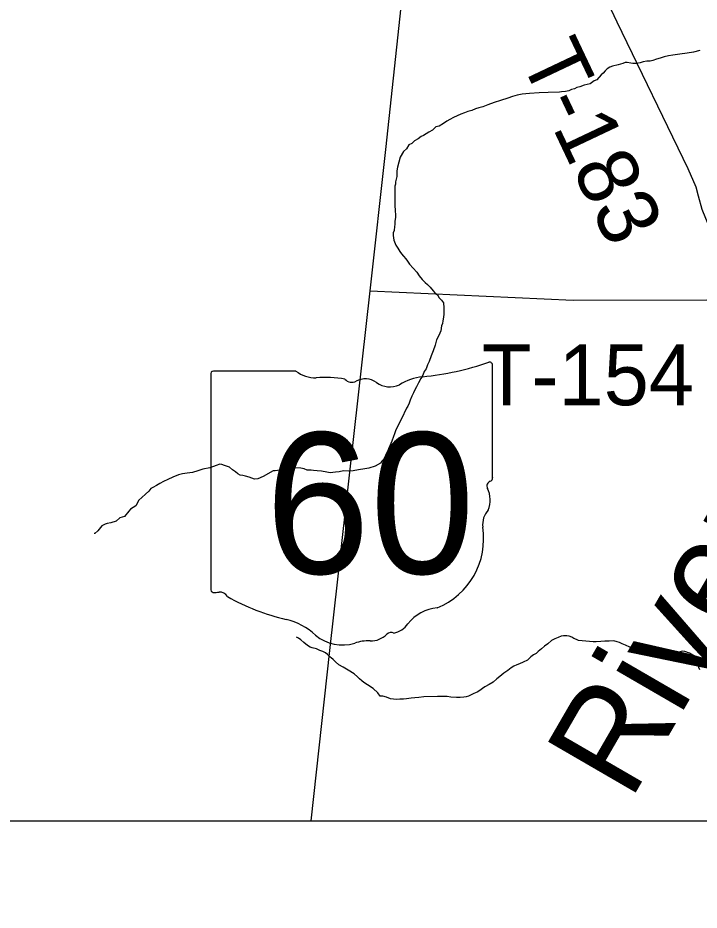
# Model space of a CAD drawing. Extents: x 0 to 34, y 0 to 22.
# Drawn here: x 4.849 to 5.486, y 15.642 to 16.477 of the extents above; entities that cross this region are included whole.
import ezdxf

# ---------------------------------------------------------------- set-up
doc = ezdxf.new("R2010")
doc.units = 0
for name, color, linetype in [('GM_X_Corporation', 7, 'Continuous'), ('GM_X_Major_River_Text', 7, 'Continuous'), ('GM_X_Minor_River', 7, 'Continuous'), ('GM_X_State_Location', 7, 'Continuous'), ('GM_X_State_Route', 7, 'Continuous'), ('GM_X_State_Shield', 7, 'Continuous'), ('GM_X_Township_Road', 7, 'Continuous'), ('GM_X_Township_Road_Text', 7, 'Continuous'), ('SH_Text', 7, 'Continuous')]:
    doc.layers.add(name, color=color, linetype=linetype)

msp = doc.modelspace()

# ---------------------------------------------------------------- linework, layer by layer
at = {"layer": 'GM_X_Corporation'}
msp.add_lwpolyline([(3.69009, 15.2048), (3.69009, 15.72564), (5.90994, 15.72564), (5.90994, 15.21376)], dxfattribs=at)
at = {"layer": 'GM_X_Minor_River'}
for points in [[(5.46154, 16.44181), (5.45735, 16.4411), (5.45353, 16.44001), (5.44972, 16.43891), (5.44629, 16.43781), (5.44285, 16.43671), (5.44018, 16.43598), (5.43714, 16.43602), (5.43371, 16.4353), (5.43104, 16.43457), (5.42761, 16.43385), (5.42419, 16.43389), (5.42229, 16.4343), (5.41888, 16.43472), (5.41698, 16.43474), (5.41469, 16.43401), (5.41049, 16.43254), (5.40515, 16.43146), (5.40248, 16.43035), (5.40018, 16.42886), (5.39826, 16.42698), (5.39633, 16.42472), (5.39441, 16.42322), (5.39056, 16.41871), (5.38788, 16.4176), (5.38405, 16.41498), (5.37871, 16.41353), (5.37451, 16.41205), (5.37184, 16.41133), (5.36955, 16.41021), (5.36688, 16.40948), (5.3642, 16.40838), (5.36115, 16.40765), (5.35735, 16.40732), (5.35544, 16.40696), (5.3448, 16.40671), (5.33643, 16.40642), (5.3273, 16.40577), (5.32045, 16.40509), (5.31588, 16.40439), (5.31168, 16.40292), (5.3071, 16.40145), (5.30023, 16.39925), (5.2945, 16.39742), (5.2884, 16.39521), (5.28381, 16.39336), (5.28, 16.39227), (5.27695, 16.39155), (5.27351, 16.39006), (5.2697, 16.38897), (5.26664, 16.38787), (5.2632, 16.38638), (5.25976, 16.38491), (5.25632, 16.38343), (5.25288, 16.38157), (5.2502, 16.38008), (5.24713, 16.37783), (5.24292, 16.37522), (5.23987, 16.3745), (5.23679, 16.37149), (5.23335, 16.36963), (5.23067, 16.36814), (5.22837, 16.36665), (5.22608, 16.36554), (5.22339, 16.36329), (5.21995, 16.36143), (5.21726, 16.35918), (5.21458, 16.35769), (5.21225, 16.35392), (5.20957, 16.35167), (5.20646, 16.34638), (5.20526, 16.34146), (5.20407, 16.33691), (5.20327, 16.3335), (5.2032, 16.32818), (5.202, 16.32325), (5.20197, 16.32097), (5.20157, 16.31907), (5.20155, 16.31717), (5.20152, 16.31451), (5.20147, 16.31109), (5.20143, 16.30767), (5.20139, 16.30387), (5.20136, 16.30159), (5.20134, 16.29969), (5.2017, 16.29778), (5.20167, 16.2955), (5.20202, 16.29284), (5.20198, 16.29018), (5.20155, 16.286), (5.20152, 16.28334), (5.20112, 16.28144), (5.20069, 16.27765), (5.1999, 16.27538), (5.19988, 16.2731), (5.20058, 16.26853), (5.20243, 16.26394), (5.2043, 16.26126), (5.20616, 16.2582), (5.20765, 16.2559), (5.20953, 16.2536)], [(5.48668, 16.44608), (5.48096, 16.44462), (5.47486, 16.44356), (5.46801, 16.4425), (5.46154, 16.44181)], [(5.20953, 16.2536), (5.21178, 16.25129), (5.21327, 16.24899), (5.21514, 16.24631), (5.22189, 16.23862), (5.22413, 16.23518), (5.22713, 16.23172), (5.22976, 16.22903), (5.23202, 16.2271), (5.23465, 16.22479), (5.23727, 16.22134), (5.23877, 16.21942), (5.2414, 16.21749), (5.24289, 16.21481), (5.24514, 16.2125), (5.24702, 16.2102), (5.24734, 16.20525), (5.24727, 16.19955), (5.24685, 16.19652), (5.24643, 16.1931), (5.24602, 16.19082), (5.24524, 16.18855), (5.24442, 16.184), (5.24247, 16.17946), (5.24052, 16.1753), (5.23932, 16.17037), (5.23735, 16.16508), (5.2354, 16.16054), (5.23343, 16.15524), (5.23188, 16.15222), (5.23069, 16.14843), (5.22876, 16.14579), (5.22757, 16.14239), (5.22564, 16.13937), (5.22369, 16.13521), (5.22174, 16.13143), (5.22019, 16.12879), (5.21901, 16.12576), (5.21746, 16.12274), (5.21589, 16.11896), (5.21472, 16.11631), (5.21354, 16.11328), (5.21238, 16.1114), (5.2077, 16.10157), (5.20576, 16.09817), (5.20497, 16.0959), (5.20342, 16.09326), (5.20224, 16.09023), (5.20107, 16.08758), (5.20027, 16.08493), (5.19871, 16.08077), (5.19675, 16.07623), (5.19558, 16.07358), (5.19479, 16.07169), (5.19362, 16.06904), (5.19245, 16.06678), (5.19128, 16.06375), (5.18935, 16.06187), (5.18819, 16.05998), (5.18322, 16.05738), (5.17711, 16.05555), (5.1733, 16.05484), (5.16759, 16.05377), (5.16264, 16.05307), (5.15807, 16.05274), (5.15351, 16.05279), (5.14932, 16.05208), (5.1459, 16.05174), (5.14361, 16.05139), (5.14095, 16.05104), (5.13792, 16.05184), (5.13298, 16.05266), (5.12881, 16.05309), (5.12539, 16.05313), (5.12311, 16.05353), (5.12121, 16.05356), (5.11931, 16.05358), (5.11666, 16.05475), (5.11363, 16.05555), (5.10869, 16.05561), (5.10299, 16.05529), (5.0965, 16.05385), (5.08965, 16.05279), (5.08775, 16.05281), (5.07818, 16.0476), (5.07322, 16.04538), (5.07017, 16.04504), (5.06525, 16.047), (5.06184, 16.0478), (5.05919, 16.04859), (5.05691, 16.049), (5.05464, 16.05016), (5.05239, 16.05209), (5.04975, 16.05402), (5.04674, 16.05634), (5.04219, 16.05791), (5.03954, 16.05871), (5.03765, 16.05911), (5.03421, 16.05801), (5.02849, 16.0558), (5.022, 16.05435)], [(5.022, 16.05435), (5.01705, 16.05289), (5.01209, 16.05143), (5.00714, 16.05073), (5.00295, 16.05002), (4.99914, 16.0493), (4.99379, 16.04709), (4.9892, 16.04486), (4.985, 16.04301), (4.98155, 16.04115), (4.97849, 16.03928), (4.97504, 16.03742), (4.97313, 16.03631), (4.9712, 16.03405), (4.96813, 16.03104), (4.96467, 16.02804), (4.96198, 16.02542), (4.95925, 16.02012), (4.95427, 16.01714), (4.95273, 16.01526), (4.94849, 16.01037), (4.94429, 16.0089), (4.94083, 16.0059), (4.93587, 16.00444), (4.93244, 16.00372), (4.93053, 16.00298), (4.92748, 16.0015), (4.92362, 15.99698), (4.92093, 15.99435), (4.92017, 15.99436)], [(5.17582, 15.85296), (5.17242, 15.8549), (5.17054, 15.85645), (5.16828, 15.85837), (5.1664, 15.8603), (5.16339, 15.86299), (5.15773, 15.86648), (5.1532, 15.8692), (5.14905, 15.87153), (5.14604, 15.87422), (5.14379, 15.87653), (5.14191, 15.87807), (5.13852, 15.88115), (5.13664, 15.8827), (5.134, 15.88387), (5.13135, 15.88504), (5.12832, 15.8866), (5.12415, 15.88741), (5.12226, 15.88819), (5.11962, 15.88974), (5.11623, 15.89244), (5.1136, 15.89475), (5.11134, 15.8963), (5.10945, 15.89746), (5.10945, 15.89746)], [(5.48693, 15.86676), (5.48582, 15.86905), (5.48546, 15.87096), (5.48511, 15.87286), (5.48252, 15.87935), (5.47724, 15.88246), (5.4727, 15.88403), (5.47042, 15.88444), (5.46508, 15.8826), (5.45936, 15.88153), (5.4548, 15.8812), (5.45214, 15.88124), (5.44986, 15.88164), (5.44644, 15.88206), (5.44454, 15.88209), (5.44189, 15.8825), (5.43885, 15.88254), (5.43504, 15.88258), (5.43238, 15.88261), (5.42898, 15.88379), (5.4271, 15.88534), (5.42445, 15.88689), (5.42143, 15.88806), (5.41727, 15.89001), (5.41424, 15.89119), (5.41159, 15.89236), (5.40932, 15.89315), (5.40629, 15.89394), (5.40211, 15.89361), (5.39793, 15.89366), (5.39412, 15.89333), (5.38993, 15.893), (5.38689, 15.89303), (5.38348, 15.89345), (5.37322, 15.89434), (5.37133, 15.89512), (5.36907, 15.89629), (5.36718, 15.89745), (5.36453, 15.89824), (5.36225, 15.89865), (5.35921, 15.89868), (5.35693, 15.89833), (5.35425, 15.89722), (5.35119, 15.89574), (5.34814, 15.89425), (5.34468, 15.89125), (5.34161, 15.88901), (5.33854, 15.88639), (5.33547, 15.88414), (5.33355, 15.88226), (5.33125, 15.88077), (5.32856, 15.8789), (5.32549, 15.8759), (5.32166, 15.87404), (5.31822, 15.87256), (5.31555, 15.87145), (5.31287, 15.87034), (5.3102, 15.86886), (5.30712, 15.86623), (5.30329, 15.86362), (5.29983, 15.86062), (5.29677, 15.85837), (5.29331, 15.85537), (5.28986, 15.85313), (5.28565, 15.8509), (5.28335, 15.84941), (5.28105, 15.84753), (5.27837, 15.84605), (5.27531, 15.84456), (5.27225, 15.84308), (5.27034, 15.84234), (5.26805, 15.84161), (5.26615, 15.84125), (5.26272, 15.84091), (5.2593, 15.84095), (5.25399, 15.84139), (5.25057, 15.84181), (5.24715, 15.84185), (5.24411, 15.84189), (5.24145, 15.84192), (5.22852, 15.84169), (5.22395, 15.84099), (5.22014, 15.84066), (5.21672, 15.84031), (5.21253, 15.8396), (5.20948, 15.83926), (5.20606, 15.8393), (5.2034, 15.83895), (5.20036, 15.83937), (5.19733, 15.83978), (5.19354, 15.84135), (5.19013, 15.84215), (5.18785, 15.84218), (5.18561, 15.84524), (5.1811, 15.84948), (5.17582, 15.85296)]]:
    msp.add_lwpolyline(points, dxfattribs=at)
at = {"layer": 'GM_X_State_Route'}
for points in [[(5.17842, 16.22124), (5.19289, 16.3535), (5.21044, 16.51624), (5.22974, 16.6939), (5.24444, 16.82177), (5.24466, 16.83668), (5.24356, 16.85335), (5.24137, 16.8698), (5.23676, 16.89107), (5.20254, 17.03583), (5.19224, 17.09461), (5.16306, 17.26613), (5.1464, 17.36833), (5.13389, 17.47471), (5.13104, 17.4984), (5.12578, 17.52647), (5.1135, 17.58328), (5.07796, 17.72968)], [(5.12323, 15.72564), (5.14069, 15.88501), (5.17842, 16.22124)]]:
    msp.add_lwpolyline(points, dxfattribs=at)
at = {"layer": 'GM_X_State_Shield'}
for p, q in [((5.29286, 16.04654), (5.29286, 16.15123)), ((5.02919, 16.14282), (5.02919, 15.9427)), ((5.109, 16.14627), (5.03179, 16.14627)), ((5.29283, 16.04657), (5.29286, 16.04654))]:
    msp.add_line(p, q, dxfattribs=at)
for centre, radius, start, end in [((5.19894, 16.4191), 0.27962, 275.84447, 288.90645), ((5.28994, 16.15166), 0.00294, 351.86209, 97.738), ((5.03221, 16.14325), 0.00305, 98.1301, 188.1301), ((5.12739, 16.1695), 0.02963, 231.61951, 271.11188), ((5.13722, 16.03392), 0.10636, 80.48669, 94.98827), ((5.16136, 16.14429), 0.00855, 219.79206, 297.10237), ((5.17391, 16.12116), 0.01777, 54.46668, 119.14113), ((5.2346, 16.08514), 0.05625, 97.34618, 120.76885), ((5.19685, 16.15288), 0.02138, 233.85621, 294.82819), ((5.29218, 16.03886), 0.00454, 107.94398, 210.33697), ((5.28973, 16.04614), 0.00314, 289.60381, 7.73413), ((5.26328, 16.02562), 0.02727, 340.03296, 23.64957), ((5.30338, 16.00273), 0.01984, 136.8065, 186.92959), ((5.2146, 15.98941), 0.06994, 292.30889, 8.98584), ((5.03224, 15.94226), 0.00308, 171.95839, 258.30661), ((5.03271, 15.96274), 0.02352, 267.33899, 280.60386), ((5.03752, 15.93116), 0.00848, 29.74838, 93.27175), ((5.14458, 16.11096), 0.20192, 240.41292, 257.1985), ((5.24409, 15.88652), 0.0383, 94.40312, 142.57675), ((5.08438, 15.8528), 0.06318, 47.18416, 75.83597), ((5.19556, 15.92331), 0.0226, 282.87319, 323.27711), ((5.15271, 15.93016), 0.04009, 230.70037, 286.29184), ((5.1788, 15.91518), 0.02136, 268.77702, 315.54927), ((5.19812, 15.8958), 0.00601, 65.75173, 132.64842), ((5.17587, 15.86098), 0.03294, 85.69512, 111.20995)]:
    msp.add_arc(centre, radius, start, end, dxfattribs=at)
at = {"layer": 'GM_X_Township_Road'}
for points in [[(5.55831, 16.21486), (5.52701, 16.24918), (5.50022, 16.27703), (5.49494, 16.28313), (5.49232, 16.28884), (5.48895, 16.29721), (5.48559, 16.30975), (5.48336, 16.31812), (5.47586, 16.33524), (5.40941, 16.47265), (5.35124, 16.59558), (5.3396, 16.61994), (5.32609, 16.64735), (5.27129, 16.76267), (5.25291, 16.80301), (5.24444, 16.82177)], [(5.17842, 16.22124), (5.36838, 16.21268), (5.49347, 16.21288), (5.55831, 16.21486)]]:
    msp.add_lwpolyline(points, dxfattribs=at)
at = {"layer": 'SH_Text'}
msp.add_lwpolyline([(3.69009, 15.72564), (5.90994, 15.72564), (5.90994, 15.00852), (3.69009, 15.00852)], close=True, dxfattribs=at)

# ---------------------------------------------------------------- texts
at = {"layer": 'GM_X_Major_River_Text'}
msp.add_text('River', height=0.094749, rotation=59.89602, dxfattribs=at).set_placement((5.42162, 15.74309))
at = {"layer": 'GM_X_State_Location'}
for s, p in [('s', (5.15806, 16.02946)), ('r', (5.15805, 16.02946))]:
    msp.add_text(s, height=0.000189, dxfattribs=at).set_placement(p)
msp.add_text('60', height=0.000189, rotation=0.00001, dxfattribs=at).set_placement((5.11037, 16.01568))
at = {"layer": 'GM_X_State_Shield'}
msp.add_text('60', height=0.131836, dxfattribs=at).set_placement((5.08022, 15.95681))
at = {"layer": 'GM_X_Township_Road_Text'}
for s, rotation, p in [('T-183', 295.34708, (5.31792, 16.43897)), ('T-154', 0.00001, (5.28286, 16.11428))]:
    msp.add_text(s, height=0.056818, rotation=rotation, dxfattribs=at).set_placement(p)

doc.saveas('drawing.dxf')
